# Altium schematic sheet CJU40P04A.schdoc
size 127 x 101 mm
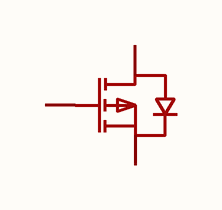
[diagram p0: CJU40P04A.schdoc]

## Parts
Q?  cju40p04a  [TO-252-2_L6.6-W6.1-P4.60-LS10.0-BR-CW]  (value not drawn)

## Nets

Not connected (* = marked no-connect by the designer): Q? 1(G) 2(D) 3(S)

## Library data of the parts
Q? = cju40p04a: 数量:1个P沟道;漏源电压(Vdss):40V;连续漏极电流(Id):40A;导通电阻(RDS(on)):22mΩ@4.5V;耗散功率(Pd):74W;阈值电压(Vgs(th)):2.5V;; Manufacturer: CJ(江苏长电/长晶); AddInBom: yes; ModelId: 2bfbfbb77002446c96d8a76a432e0188; ModelTransform: 246.80147,383.8575,0,90,0,0,-31.302,0.003,0; Number: 1个P沟道; Drain to Source Voltage: 40V; Current - Continuous Drain(Id): 40A; Pd - Power Dissipation: 74W; Gate Threshold Voltage (Vgs(th)): 2.5V; Gate Charge(Qg): 46nC@4.5V; Input Capacitance(Ciss): 4.6nF; Reverse Transfer Capacitance (Crss@Vds): 300pF; Type: P沟道; Output Capacitance(Coss): 480pF; Vgs: ±20V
